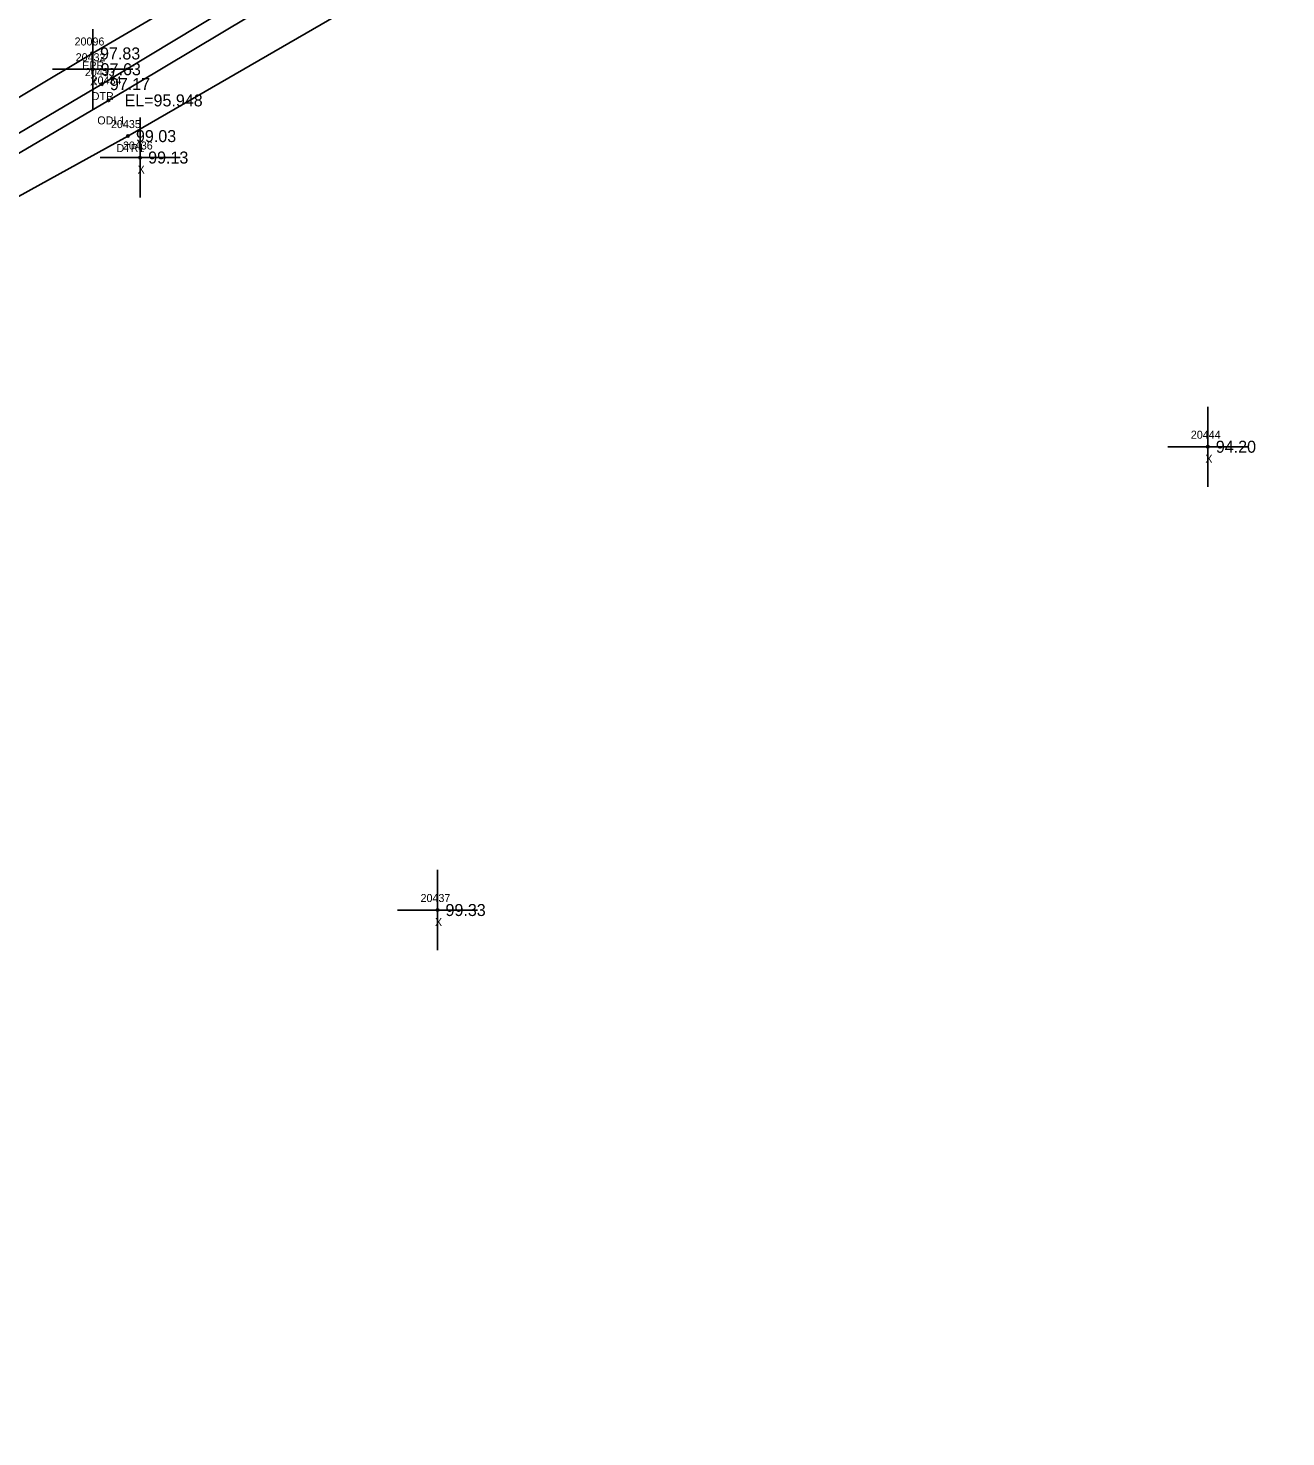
# Model space of a CAD drawing. Extents: x 2530197 to 2532051, y 935230 to 936631.
# Drawn here: x 2530787.5 to 2530944.6, y 935579.5 to 935755.5 of the extents above; entities that cross this region are included whole.
import ezdxf

# ---------------------------------------------------------------- set-up
doc = ezdxf.new("R2010")
doc.units = 0
for name, color, linetype in [('RD_EX_H2O', 7, 'Continuous'), ('RD_EX_H2O_txCode', 7, 'Continuous'), ('RD_EX_Misc', 7, 'Continuous'), ('RD_EX_Misc_txCode', 7, 'Continuous'), ('RD_EX_Road', 7, 'Continuous'), ('RD_EX_Road_txCode', 7, 'Continuous'), ('RD_EX_TX_H2O_ELEV', 7, 'Continuous'), ('RD_EX_TX_Misc_ELEV', 7, 'Continuous'), ('RD_EX_TX_Road_ELEV', 7, 'Continuous'), ('RD_SMD_Locator', 7, 'Continuous')]:
    doc.layers.add(name, color=color, linetype=linetype)

msp = doc.modelspace()

# ---------------------------------------------------------------- linework, layer by layer
at = {"layer": 'RD_EX_H2O'}
for points in [[(2530722.38, 935704.62), (2530796.68, 935748.53), (2530872.47, 935794.26), (2530874.44, 935791.96), (2530875.06, 935785.48)], [(2530724.37, 935703.48), (2530797.51, 935746.5), (2530871.29, 935790.63)], [(2530722.38, 935704.62), (2530722.37, 935702.56), (2530725.17, 935700.81), (2530799.94, 935742.04), (2530875.06, 935785.48)]]:
    msp.add_lwpolyline(points, dxfattribs=at)
at = {"layer": 'RD_EX_Misc'}
for p, q in [((2530795.53, 935745.39), (2530795.53, 935755.39)), ((2530790.53, 935750.39), (2530800.53, 935750.39)), ((2530801.46, 935734.36), (2530801.46, 935744.36)), ((2530796.46, 935739.36), (2530806.46, 935739.36)), ((2530934.84, 935698.23), (2530934.84, 935708.23)), ((2530929.84, 935703.23), (2530939.84, 935703.23)), ((2530838.61, 935640.35), (2530838.61, 935650.35)), ((2530833.61, 935645.35), (2530843.61, 935645.35))]:
    msp.add_line(p, q, dxfattribs=at)
at = {"layer": 'RD_EX_Road'}
msp.add_lwpolyline([(2530212.44, 935579.72), (2530312.61, 935580.14), (2530402.98, 935580.64), (2530451.06, 935579.53), (2530466.91, 935580.35), (2530487.45, 935583.29), (2530533.43, 935598.45), (2530580.28, 935625.08), (2530621.69, 935649.23), (2530704.62, 935698.35), (2530718.67, 935706.38), (2530795.45, 935752.36), (2530871.33, 935796.67), (2530882.4, 935803.04), (2530947.17, 935842.26), (2530966, 935852.42), (2530992.72, 935868), (2531009.49, 935879.01), (2531052.39, 935904.85), (2531090.88, 935928.23)], dxfattribs=at)
at = {"layer": 'RD_SMD_Locator'}
for centre in [(2530795.45, 935752.36), (2530795.53, 935750.39), (2530796.68, 935748.53), (2530797.51, 935746.5), (2530799.94, 935742.04), (2530801.46, 935739.36), (2530934.84, 935703.23), (2530838.61, 935645.35)]:
    msp.add_circle(centre, 0.15, dxfattribs=at)

# ---------------------------------------------------------------- texts
at = {"layer": 'RD_EX_H2O_txCode'}
for s, p in [('20433', (2530794.56, 935749.53)), ('20434', (2530795.4, 935748.5)), ('DTR', (2530795.41, 935746.53)), ('ODL1', (2530796.11, 935743.5)), ('20435', (2530797.82, 935743.04)), ('DTR1', (2530798.5, 935740.04))]:
    msp.add_text(s, height=1, dxfattribs=at).set_placement(p)
at = {"layer": 'RD_EX_Misc_txCode'}
for s, p in [('20432', (2530793.41, 935751.39)), ('X', (2530795.21, 935748.39)), ('20436', (2530799.31, 935740.36)), ('X', (2530801.14, 935737.36)), ('20444', (2530932.72, 935704.23)), ('X', (2530934.53, 935701.23)), ('20437', (2530836.49, 935646.35)), ('X', (2530838.29, 935643.35))]:
    msp.add_text(s, height=1, dxfattribs=at).set_placement(p)
at = {"layer": 'RD_EX_Road_txCode'}
for s, p in [('20096', (2530793.27, 935753.36)), ('EPR', (2530794.22, 935750.36))]:
    msp.add_text(s, height=1, dxfattribs=at).set_placement(p)
at = {"layer": 'RD_EX_TX_H2O_ELEV'}
for s, p in [('97.17', (2530797.68, 935747.78)), ('EL=95.948', (2530799.51, 935745.75)), ('99.03', (2530800.94, 935741.29))]:
    msp.add_text(s, height=1.5, dxfattribs=at).set_placement(p)
at = {"layer": 'RD_EX_TX_Misc_ELEV'}
for s, p in [('97.63', (2530796.53, 935749.64)), ('99.13', (2530802.46, 935738.61)), ('94.20', (2530935.84, 935702.48)), ('99.33', (2530839.61, 935644.6))]:
    msp.add_text(s, height=1.5, dxfattribs=at).set_placement(p)
at = {"layer": 'RD_EX_TX_Road_ELEV'}
msp.add_text('97.83', height=1.5, dxfattribs=at).set_placement((2530796.45, 935751.61))

doc.saveas('drawing.dxf')
